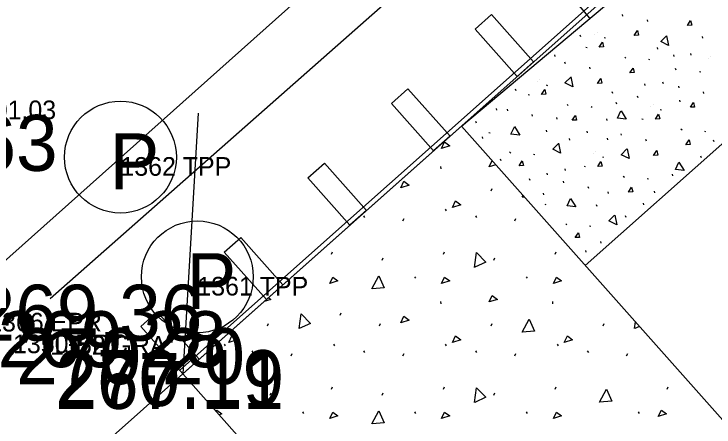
# Model space of a CAD drawing. Extents: x 49683 to 58852, y 49525 to 54803.
# Drawn here: x 53900.13 to 53937.68, y 51862.44 to 51884.59 of the extents above; entities that cross this region are included whole.
import ezdxf

# ---------------------------------------------------------------- set-up
doc = ezdxf.new("R2010")
doc.units = 0
for name, color, linetype in [('Level 15', 7, 'Continuous'), ('Level 20', 7, 'Continuous'), ('Level 27', 7, 'Continuous'), ('Level 3', 7, 'Continuous'), ('Level 32', 7, 'Continuous'), ('Level 48', 7, 'Continuous'), ('Level 51', 7, 'Continuous'), ('Level 53', 7, 'Continuous'), ('Level 55', 7, 'Continuous'), ('Level 57', 7, 'Continuous'), ('Level 59', 7, 'Continuous'), ('Level 7', 7, 'Continuous'), ('Level 8', 7, 'Continuous'), ('Level 9', 7, 'Continuous')]:
    doc.layers.add(name, color=color, linetype=linetype)

# ---------------------------------------------------------------- blocks, each defined once
blk = doc.blocks.new('TPP')
at = {"layer": 'Level 9'}
blk.add_circle((0, 0), 3, dxfattribs=at)
blk.add_text('P', height=3, dxfattribs=at).set_placement((-0.589, -1.729))

msp = doc.modelspace()

# ---------------------------------------------------------------- linework, layer by layer
at = {"layer": 'Level 15'}
for p, q in [((53910.003, 51879.272), (53909.18, 51865.296)), ((53909.18, 51865.296), (53924.129, 51878.584)), ((53924.129, 51878.584), (53953.361, 51845.698)), ((53923.006, 51876.413), (53923.02, 51876.288)), ((53925.731, 51875.108), (53925.786, 51875.233)), ((53923.263, 51874.123), (53923.318, 51874.04)), ((53918.882, 51873.77), (53918.937, 51873.687)), ((53920.993, 51873.499), (53921.049, 51873.623)), ((53924.882, 51873.77), (53924.937, 51873.687)), ((53926.993, 51873.499), (53927.049, 51873.623)), ((53917.158, 51871.709), (53917.213, 51871.834)), ((53923.158, 51871.709), (53923.213, 51871.834)), ((53929.158, 51871.709), (53929.213, 51871.834)), ((53919.869, 51871.39), (53919.925, 51871.514)), ((53925.869, 51871.39), (53925.925, 51871.514)), ((53915.604, 51870.502), (53915.659, 51870.418)), ((53921.604, 51870.502), (53921.659, 51870.418)), ((53927.604, 51870.502), (53927.659, 51870.418)), ((53923.006, 51869.171), (53923.02, 51869.046)), ((53929.006, 51869.171), (53929.02, 51869.046)), ((53917.622, 51868.434), (53917.677, 51868.559)), ((53913.731, 51867.865), (53913.786, 51867.99)), ((53919.731, 51867.865), (53919.786, 51867.99)), ((53925.731, 51867.865), (53925.786, 51867.99)), ((53931.731, 51867.865), (53931.786, 51867.99)), ((53911.406, 51866.881), (53911.461, 51866.797)), ((53917.263, 51866.881), (53917.318, 51866.797)), ((53923.263, 51866.881), (53923.318, 51866.797)), ((53929.263, 51866.881), (53929.318, 51866.797)), ((53912.882, 51866.527), (53912.937, 51866.444)), ((53914.993, 51866.256), (53915.049, 51866.381)), ((53918.882, 51866.527), (53918.937, 51866.444)), ((53920.993, 51866.256), (53921.049, 51866.381)), ((53924.882, 51866.527), (53924.937, 51866.444)), ((53926.993, 51866.256), (53927.049, 51866.381)), ((53930.882, 51866.527), (53930.937, 51866.444)), ((53932.993, 51866.256), (53933.049, 51866.381)), ((53460.734, 51466.679), (53909.18, 51865.296)), ((53938.412, 51832.41), (53909.18, 51865.296)), ((53911.301, 51864.466), (53911.356, 51864.591)), ((53917.158, 51864.466), (53917.213, 51864.591)), ((53923.158, 51864.466), (53923.213, 51864.591)), ((53929.158, 51864.466), (53929.213, 51864.591)), ((53935.158, 51864.466), (53935.213, 51864.591)), ((53913.869, 51864.147), (53913.925, 51864.272)), ((53919.869, 51864.147), (53919.925, 51864.272)), ((53925.869, 51864.147), (53925.925, 51864.272)), ((53915.604, 51863.259), (53915.659, 51863.176)), ((53921.604, 51863.259), (53921.659, 51863.176)), ((53927.604, 51863.259), (53927.659, 51863.176)), ((53933.604, 51863.259), (53933.659, 51863.176))]:
    msp.add_line(p, q, dxfattribs=at)
for points in [[(53923.061, 51877.384), (53923.227, 51877.73), (53923.505, 51877.522), (53923.061, 51877.384)], [(53925.614, 51876.392), (53925.776, 51876.73)], [(53925.976, 51876.505), (53925.614, 51876.392)], [(53920.874, 51875.278), (53921.04, 51875.625), (53921.318, 51875.417), (53920.874, 51875.278)], [(53923.649, 51874.22), (53923.816, 51874.567), (53924.093, 51874.359), (53923.649, 51874.22)], [(53927.379, 51874.766), (53927.432, 51874.867)], [(53927.513, 51874.776), (53927.393, 51874.766)], [(53924.829, 51871.002), (53924.939, 51871.795), (53925.436, 51871.282), (53924.842, 51871.007)], [(53917.061, 51870.141), (53917.227, 51870.488), (53917.505, 51870.28), (53917.061, 51870.141)], [(53919.318, 51869.851), (53919.692, 51870.559), (53919.984, 51869.907), (53919.331, 51869.851)], [(53923.061, 51870.141), (53923.227, 51870.488), (53923.505, 51870.28), (53923.061, 51870.141)], [(53929.061, 51870.141), (53929.227, 51870.488), (53929.505, 51870.28), (53929.061, 51870.141)], [(53913.776, 51869.381), (53913.9, 51869.288), (53913.547, 51869.178)], [(53925.614, 51869.149), (53925.781, 51869.496), (53926.058, 51869.288), (53925.614, 51869.149)], [(53915.419, 51867.722), (53915.529, 51868.515), (53916.026, 51868.002), (53915.432, 51867.727)], [(53920.874, 51868.035), (53921.04, 51868.382), (53921.318, 51868.174), (53920.874, 51868.035)], [(53927.379, 51867.523), (53927.754, 51868.231), (53928.045, 51867.579), (53927.393, 51867.523)], [(53933.419, 51867.722), (53933.468, 51868.077)], [(53933.678, 51867.841), (53933.432, 51867.727)], [(53911.649, 51866.977), (53911.816, 51867.324), (53912.093, 51867.116), (53911.649, 51866.977)], [(53923.649, 51866.977), (53923.816, 51867.324), (53924.093, 51867.116), (53923.649, 51866.977)], [(53929.649, 51866.977), (53929.816, 51867.324), (53930.093, 51867.116), (53929.649, 51866.977)], [(53924.829, 51863.759), (53924.939, 51864.552), (53925.436, 51864.039), (53924.842, 51863.764)], [(53931.529, 51863.772), (53931.904, 51864.48), (53932.195, 51863.828), (53931.543, 51863.772)], [(53910.968, 51863.285), (53911, 51863.351), (53911.277, 51863.143), (53911.134, 51863.098)], [(53919.318, 51862.609), (53919.692, 51863.316), (53919.984, 51862.664), (53919.331, 51862.609)], [(53934.691, 51863.004), (53934.857, 51863.351), (53935.135, 51863.143), (53934.691, 51863.004)], [(53917.061, 51862.898), (53917.227, 51863.245), (53917.505, 51863.037), (53917.061, 51862.898)], [(53923.061, 51862.898), (53923.227, 51863.245), (53923.505, 51863.037), (53923.061, 51862.898)], [(53929.061, 51862.898), (53929.227, 51863.245), (53929.505, 51863.037), (53929.061, 51862.898)]]:
    msp.add_lwpolyline(points, dxfattribs=at)
at = {"layer": 'Level 20'}
msp.add_line((53930.772, 51871.11), (54173.795, 52087.129), dxfattribs=at)
at = {"layer": 'Level 27'}
for p, q in [((53909.014, 51865.483), (53951.064, 51902.86)), ((53909.18, 51865.296), (53951.23, 51902.673)), ((53924.86, 51883.783), (53925.743, 51884.568)), ((53925.743, 51884.568), (53928.002, 51882.026)), ((53927.118, 51881.241), (53924.86, 51883.783)), ((53928.002, 51882.026), (53927.118, 51881.241)), ((53920.375, 51879.796), (53921.259, 51880.582)), ((53921.259, 51880.582), (53923.517, 51878.04)), ((53922.634, 51877.255), (53920.375, 51879.796)), ((53923.517, 51878.04), (53922.634, 51877.255)), ((53915.891, 51875.81), (53916.774, 51876.595)), ((53916.774, 51876.595), (53919.033, 51874.054)), ((53918.149, 51873.269), (53915.891, 51875.81)), ((53919.033, 51874.054), (53918.149, 51873.269)), ((53911.406, 51871.824), (53912.29, 51872.609)), ((53912.29, 51872.609), (53914.548, 51870.068)), ((53913.665, 51869.283), (53911.406, 51871.824)), ((53914.548, 51870.068), (53913.665, 51869.283)), ((53906.922, 51867.838), (53907.806, 51868.623)), ((53907.806, 51868.623), (53910.064, 51866.082)), ((53909.18, 51865.296), (53906.922, 51867.838)), ((53910.064, 51866.082), (53909.18, 51865.296))]:
    msp.add_line(p, q, dxfattribs=at)
at = {"layer": 'Level 3'}
msp.add_line((53898.742, 51870.567), (54083.389, 52035.124), dxfattribs=at)
at = {"layer": 'Level 7'}
msp.add_line((53902.065, 51869.327), (53922.854, 51887.665), dxfattribs=at)
at = {"layer": 'Level 8'}
for p, q in [((53931.026, 51884.365), (53921.496, 51895.735)), ((53924.129, 51878.584), (53935.625, 51888.219)), ((53932.754, 51884.572), (53932.778, 51884.484)), ((53934.086, 51884.278), (53934.11, 51884.19)), ((53931.413, 51883.612), (53931.413, 51883.612)), ((53930.483, 51883.47), (53930.508, 51883.382)), ((53931.285, 51883.506), (53931.285, 51883.506)), ((53931.85, 51883.289), (53931.786, 51883.309)), ((53937.038, 51883.389), (53937.062, 51883.301)), ((53930.867, 51882.786), (53930.803, 51882.805)), ((53934.632, 51882.801), (53934.656, 51882.713)), ((53936.412, 51882.472), (53936.436, 51882.384)), ((53929.124, 51882.401), (53929.148, 51882.313)), ((53932.952, 51882.219), (53932.891, 51882.277)), ((53934.237, 51882.127), (53934.174, 51882.147)), ((53935.507, 51882.405), (53935.531, 51882.317)), ((53937.385, 51882.191), (53937.385, 51882.191)), ((53937.513, 51882.296), (53937.513, 51882.296)), ((53929.664, 51882.031), (53929.689, 51881.943)), ((53930.996, 51881.737), (53931.02, 51881.649)), ((53935.602, 51881.694), (53935.627, 51881.606)), ((53936.967, 51881.47), (53936.903, 51881.49)), ((53928.195, 51880.965), (53928.195, 51880.965)), ((53928.324, 51881.071), (53928.324, 51881.071)), ((53934.923, 51880.949), (53934.947, 51880.861)), ((53927.019, 51880.586), (53927.044, 51880.498)), ((53928.76, 51880.749), (53928.696, 51880.768)), ((53933.948, 51880.848), (53933.973, 51880.76)), ((53935.765, 51880.716), (53935.789, 51880.628)), ((53927.777, 51880.245), (53927.713, 51880.264)), ((53932.204, 51880.436), (53932.228, 51880.348)), ((53933.563, 51880.209), (53933.588, 51880.121)), ((53937.096, 51880.422), (53937.121, 51880.334)), ((53932.417, 51879.864), (53932.441, 51879.776)), ((53935.829, 51879.977), (53935.853, 51879.889)), ((53925.988, 51879.523), (53926.012, 51879.435)), ((53926.575, 51879.491), (53926.599, 51879.403)), ((53929.862, 51879.678), (53929.802, 51879.736)), ((53931.148, 51879.587), (53931.084, 51879.606)), ((53934.295, 51879.65), (53934.295, 51879.65)), ((53934.424, 51879.756), (53934.424, 51879.756)), ((53934.86, 51879.433), (53934.797, 51879.453)), ((53927.907, 51879.197), (53927.931, 51879.109)), ((53924.887, 51878.842), (53924.911, 51878.755)), ((53929.225, 51879.042), (53929.25, 51878.954)), ((53931.912, 51878.972), (53931.936, 51878.884)), ((53933.877, 51878.929), (53933.813, 51878.949)), ((53928.675, 51878.362), (53928.699, 51878.274)), ((53930.859, 51878.307), (53930.883, 51878.219)), ((53935.962, 51878.363), (53935.902, 51878.421)), ((53925.243, 51878), (53925.267, 51877.912)), ((53925.671, 51878.208), (53925.607, 51878.227)), ((53931.944, 51877.935), (53931.969, 51877.847)), ((53932.675, 51878.175), (53932.699, 51878.087)), ((53937.248, 51878.271), (53937.184, 51878.291)), ((53929.905, 51877.908), (53929.929, 51877.82)), ((53934.007, 51877.881), (53934.031, 51877.793)), ((53937.642, 51877.843), (53937.667, 51877.755)), ((53926.773, 51877.137), (53926.713, 51877.196)), ((53931.335, 51877.215), (53931.335, 51877.215)), ((53926.214, 51876.833), (53926.238, 51876.745)), ((53928.059, 51877.046), (53927.995, 51877.065)), ((53931.206, 51877.109), (53931.206, 51877.109)), ((53931.771, 51876.892), (53931.707, 51876.912)), ((53936.959, 51876.992), (53936.983, 51876.904)), ((53928.707, 51876.056), (53928.731, 51875.968)), ((53929.678, 51876.282), (53929.702, 51876.195)), ((53930.788, 51876.389), (53930.724, 51876.408)), ((53927.77, 51875.766), (53927.794, 51875.678)), ((53932.873, 51875.822), (53932.813, 51875.88)), ((53934.159, 51875.73), (53934.095, 51875.75)), ((53935.428, 51876.008), (53935.452, 51875.92)), ((53929.586, 51875.634), (53929.61, 51875.547)), ((53930.917, 51875.34), (53930.942, 51875.252)), ((53928.513, 51874.986), (53928.537, 51874.898)), ((53931.977, 51875.057), (53932.001, 51874.969)), ((53934.47, 51875.089), (53934.494, 51875.001)), ((53928.682, 51874.352), (53928.618, 51874.371)), ((53931.362, 51874.376), (53931.386, 51874.288)), ((53933.87, 51874.451), (53933.894, 51874.363)), ((53932.916, 51873.793), (53932.94, 51873.705)), ((53929.783, 51873.281), (53929.723, 51873.339)), ((53931.069, 51873.19), (53931.005, 51873.209)), ((53931.589, 51872.399), (53931.613, 51872.311)), ((53930.78, 51871.91), (53930.805, 51871.822))]:
    msp.add_line(p, q, dxfattribs=at)
for points in [[(53936.424, 51884.237), (53936.485, 51883.988), (53936.254, 51883.978), (53936.424, 51884.237)], [(53933.569, 51883.706), (53933.63, 51883.457), (53933.399, 51883.447), (53933.569, 51883.706)], [(53935.139, 51883.43), (53935.246, 51882.908), (53934.82, 51883.12), (53935.132, 51883.425)], [(53931.692, 51883.076), (53931.753, 51882.827), (53931.522, 51882.816), (53931.692, 51883.076)], [(53933.335, 51881.696), (53933.396, 51881.447), (53933.165, 51881.437), (53933.335, 51881.696)], [(53930.003, 51881.215), (53930.109, 51880.692), (53929.683, 51880.905), (53929.995, 51881.209)], [(53931.6, 51881.125), (53931.661, 51880.876), (53931.43, 51880.866), (53931.6, 51881.125)], [(53928.602, 51880.535), (53928.664, 51880.286), (53928.432, 51880.276), (53928.602, 51880.535)], [(53936.58, 51879.85), (53936.641, 51879.601), (53936.41, 51879.591), (53936.58, 51879.85)], [(53930.245, 51879.155), (53930.306, 51878.906), (53930.075, 51878.896), (53930.245, 51879.155)], [(53932.692, 51879.402), (53932.971, 51878.948), (53932.498, 51879.001), (53932.687, 51879.394)], [(53934.703, 51879.22), (53934.764, 51878.971), (53934.533, 51878.96), (53934.703, 51879.22)], [(53926.977, 51878.556), (53927.256, 51878.101), (53926.783, 51878.154), (53926.972, 51878.548)], [(53929.344, 51877.66), (53929.451, 51877.137), (53929.025, 51877.349), (53929.337, 51877.654)], [(53936.345, 51877.84), (53936.407, 51877.591), (53936.175, 51877.581), (53936.345, 51877.84)], [(53933.013, 51877.359), (53933.12, 51876.836), (53932.694, 51877.048), (53933.006, 51877.353)], [(53934.61, 51877.269), (53934.672, 51877.02), (53934.441, 51877.01), (53934.61, 51877.269)], [(53927.391, 51876.717), (53927.452, 51876.468), (53927.221, 51876.457), (53927.391, 51876.717)], [(53931.613, 51876.679), (53931.674, 51876.43), (53931.443, 51876.419), (53931.613, 51876.679)], [(53935.8, 51876.648), (53936.079, 51876.193), (53935.606, 51876.247), (53935.795, 51876.64)], [(53933.256, 51875.299), (53933.317, 51875.05), (53933.086, 51875.04), (53933.256, 51875.299)], [(53929.987, 51874.699), (53930.267, 51874.244), (53929.794, 51874.298), (53929.983, 51874.691)], [(53932.355, 51873.804), (53932.462, 51873.281), (53932.036, 51873.493), (53932.348, 51873.798)], [(53930.402, 51872.861), (53930.463, 51872.612), (53930.232, 51872.601), (53930.402, 51872.861)]]:
    msp.add_lwpolyline(points, dxfattribs=at)

# ---------------------------------------------------------------- block references
at = {"layer": 'Level 9'}
for p in [(53905.834, 51876.918), (53909.962, 51870.495)]:
    msp.add_blockref('TPP', p, dxfattribs=at)

# ---------------------------------------------------------------- texts
at = {"layer": 'Level 32'}
for s, p in [('269.63', (53890.195, 51876.179)), ('269.36', (53897.959, 51867.074)), ('269.28', (53899.247, 51865.651)), ('270.20', (53900.245, 51864.74)), ('270.19', (53902.346, 51863.565)), ('267.11', (53902.346, 51863.413))]:
    msp.add_text(s, height=3, dxfattribs=at).set_placement(p)
at = {"layer": 'Level 48'}
msp.add_text("44'C", height=5, rotation=41.6334, dxfattribs=at).set_placement((53894.5, 51881.812))
at = {"layer": 'Level 51'}
msp.add_text('12 POT 523+01.03', height=1, dxfattribs=at).set_placement((53891.047, 51878.951))
at = {"layer": 'Level 53'}
msp.add_text('1366 EPR', height=1, dxfattribs=at).set_placement((53898.742, 51867.567))
at = {"layer": 'Level 55'}
msp.add_text('1350 BRC', height=1, dxfattribs=at).set_placement((53900.074, 51866.402))
at = {"layer": 'Level 57'}
msp.add_text('1352 GRA', height=1, dxfattribs=at).set_placement((53902.065, 51866.327))
at = {"layer": 'Level 59'}
for s, p in [('1362 TPP', (53905.834, 51875.918)), ('1361 TPP', (53909.962, 51869.495))]:
    msp.add_text(s, height=1, dxfattribs=at).set_placement(p)

doc.saveas('drawing.dxf')
